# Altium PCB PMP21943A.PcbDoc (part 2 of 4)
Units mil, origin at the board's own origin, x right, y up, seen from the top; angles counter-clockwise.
Board outline 5100 x 3900 mil, 8 copper layers (Top Layer, Signal Layer 1, Signal Layer 2, Signal Layer 3, Signal Layer 4, Signal Layer 5, Signal Layer 6, Bottom Layer), stack 61.6 mil thick; 371 components, 163 nets, 967 pads, 1147 vias.
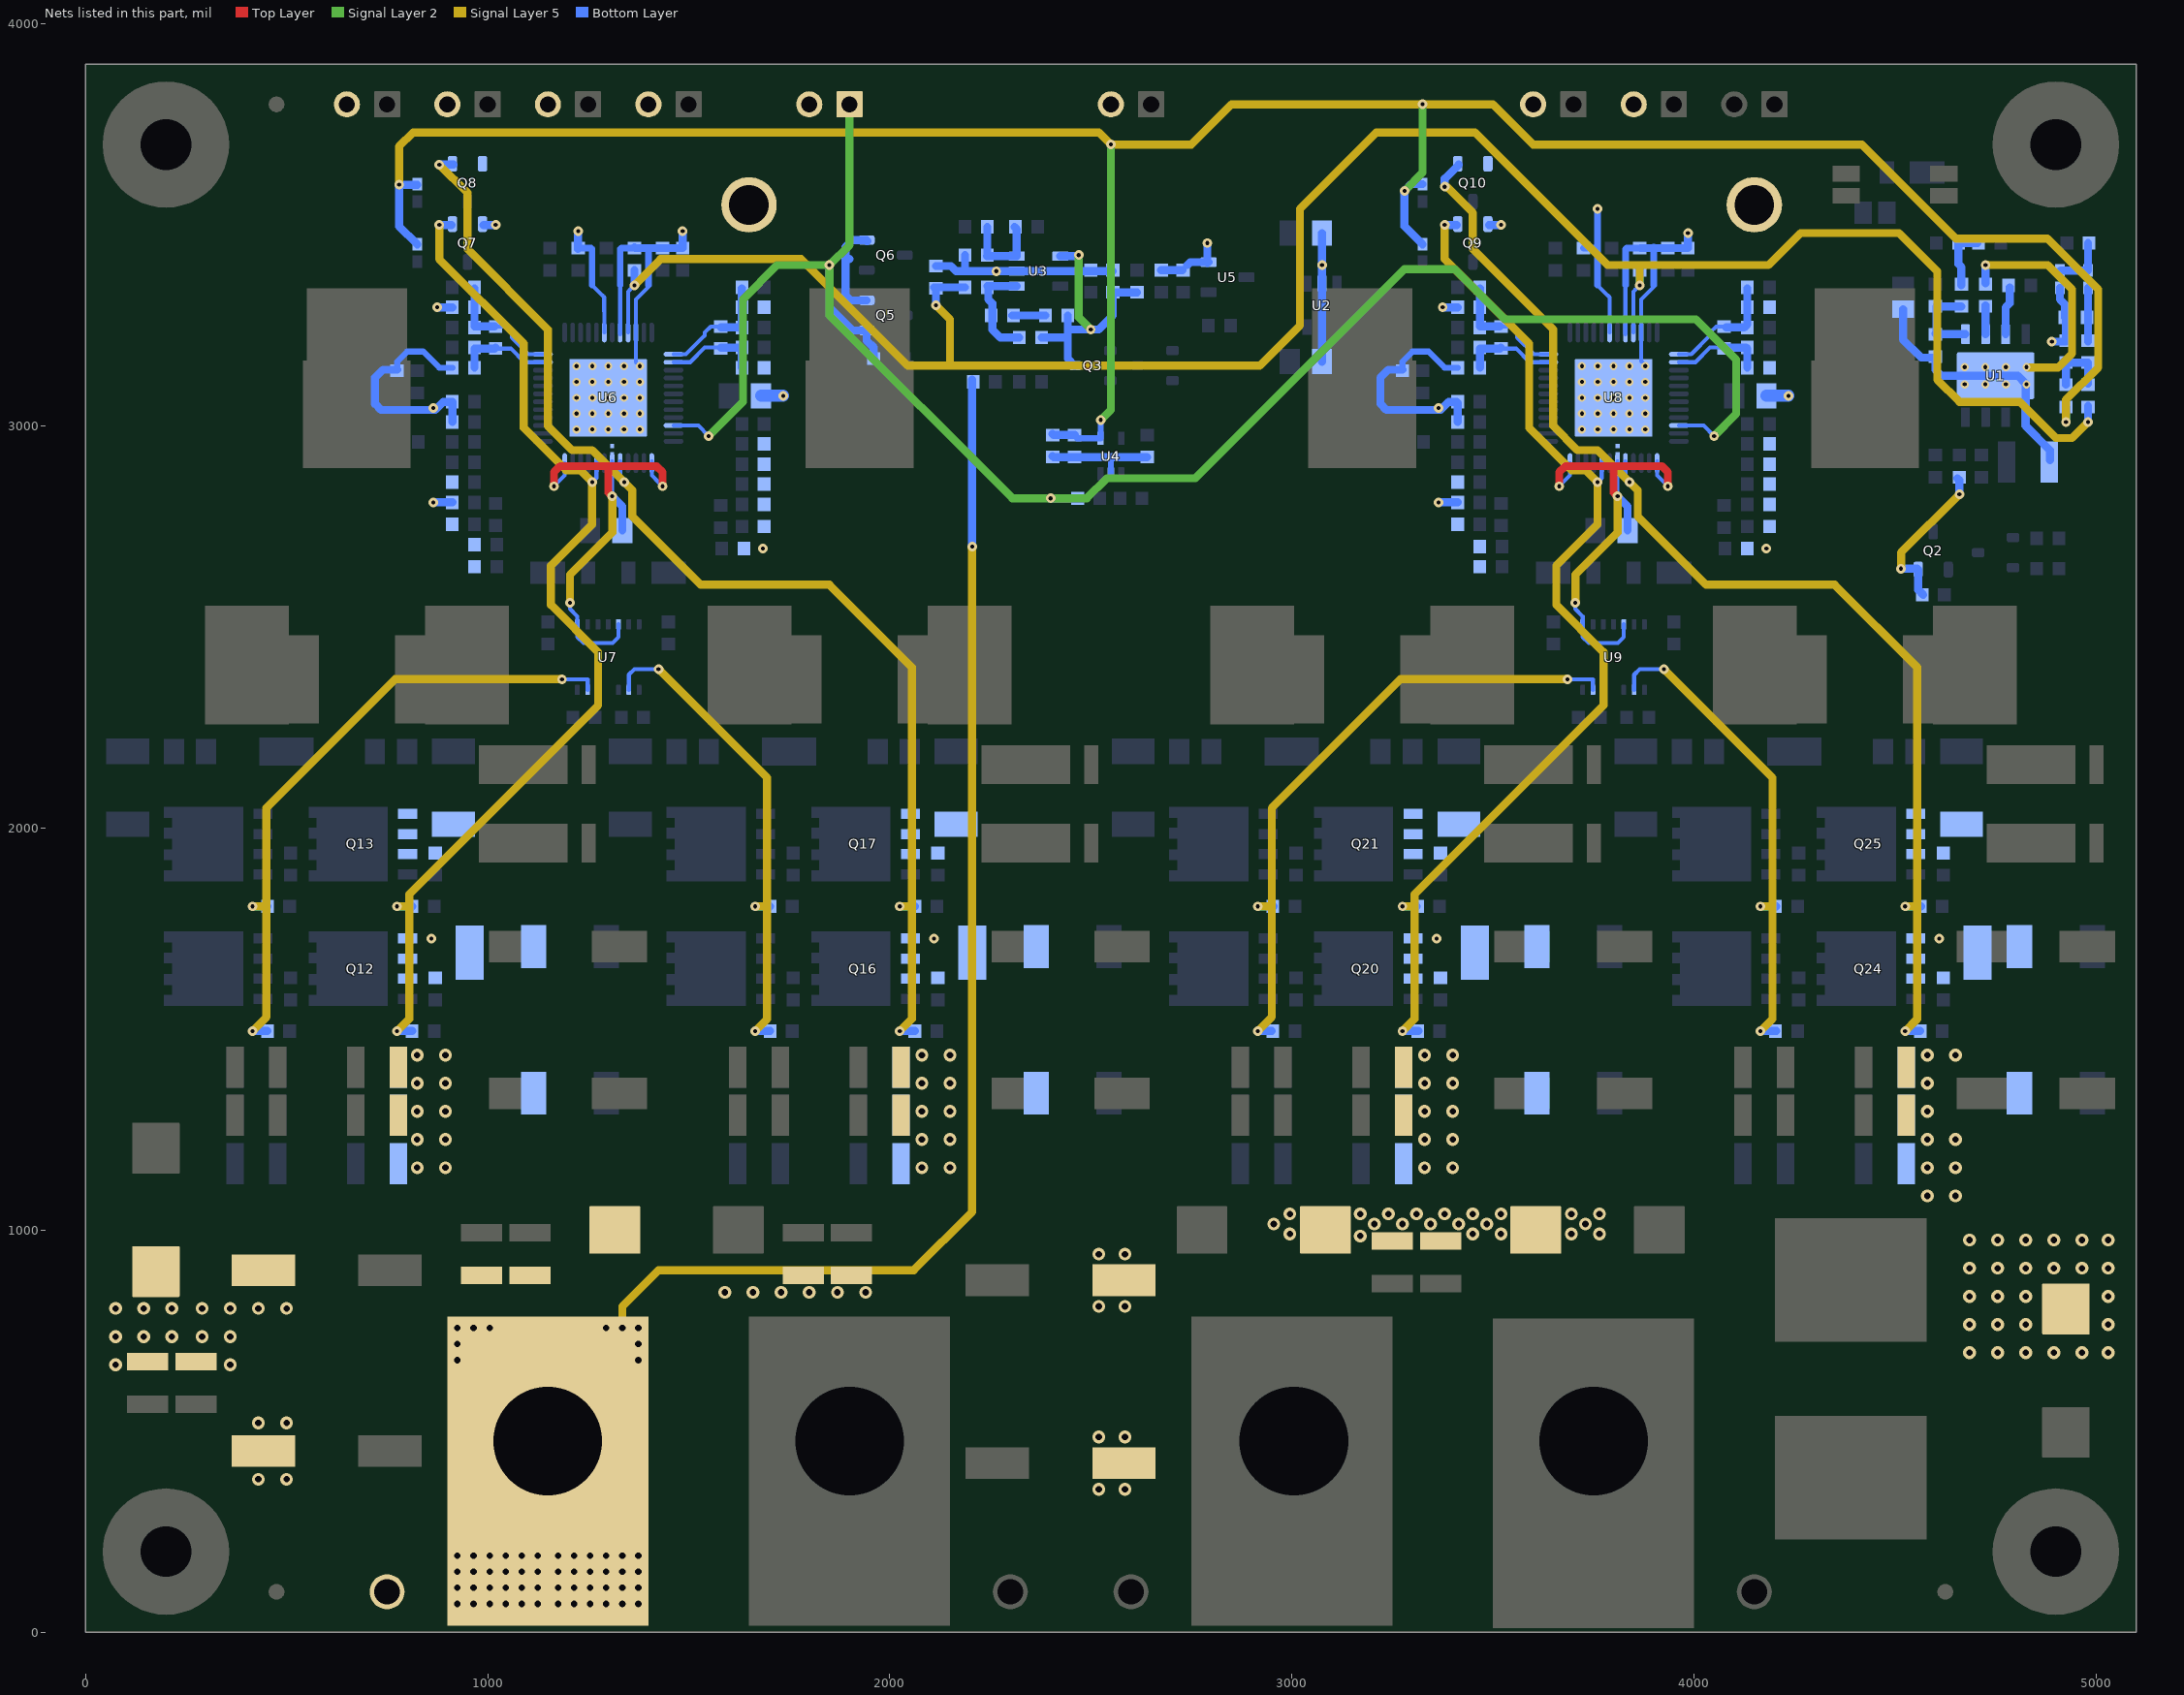
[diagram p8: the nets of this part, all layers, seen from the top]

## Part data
C1 C8: library part CMP-0007995-2, "CAP, CERM, 10 uF, 16 V, +/- 10%, X7R, 0805", Cap_Case=0805, Manufacturer="Samsung Electro-Mechanics", PartNumber=CL21B106KOQNNNE, TempCo=X7R, Tolerance_%=10%, Value1=Unknown, Value2=16V, ValueDisplayed=10uF
C2 C11: library part CMP-0007468-5, "CAP, CERM, 0.01 uF, 100 V, +/- 10%, X7R, 0603", Cap_Case=0603, Manufacturer=MuRata, PartNumber=GRM188R72A103KA01D, Supplier Part Number 1=GRM188R72A103KA01D-ND, TempCo=X7R, Tolerance_%=10%, Value1=Unknown, Value2=100V, ValueDisplayed=0.01uF
C3 C24 C45: library part CMP-0007891-2, "CAP, CERM, 1 uF, 100 V, +/- 10%, X7S, 0805", Cap_Case=0805, Manufacturer=TDK, PartNumber=C2012X7S2A105K125AB, Supplier Part Number 1=445-5205-1-ND, TempCo=X7S, Tolerance_%=10%, Value1="0.008255 ohm", Value2=100V, ValueDisplayed=1uF
C4: library part CMP-0006883-4, "CAP, CERM, 0.015 uF, 100 V, +/- 10%, X7R, 0603", Cap_Case=0603, Manufacturer=Kemet, PartNumber=C0603C153K1RACTU, Supplier Part Number 1=399-3474-1-ND, TempCo=X7R, Tolerance_%=10%, Value1=Unknown, Value2=100V, ValueDisplayed=0.015uF
C5: library part CMP-0007379-4, "CAP, CERM, 1 uF, 16 V, +/- 10%, X7R, 0603", Cap_Case=0603, Manufacturer=MuRata, PartNumber=GRM188R71C105KA12D, Supplier Part Number 1=490-3900-1-ND, TempCo=X7R, Tolerance_%=10%, Value1="0.011 ohm", Value2=16V, ValueDisplayed=1uF
C6 C29 C50: library part CMP-0007867-2, "CAP, CERM, 2.2 uF, 16 V, +/- 10%, X7R, 0805", Cap_Case=0805, Manufacturer=TDK, PartNumber=C2012X7R1C225K125AB, Supplier Part Number 1=445-1420-1-ND, TempCo=X7R, Tolerance_%=10%, Value1="0.0049 ohm", Value2=16V, ValueDisplayed=2.2uF
C7: library part CMP-0007467-4, "CAP, CERM, 1000 pF, 100 V, +/- 10%, X7R, 0603", Cap_Case=0603, Manufacturer=MuRata, PartNumber=GRM188R72A102KA01D, Supplier Part Number 1=490-1472-1-ND, TempCo=X7R, Tolerance_%=10%, Value1=Unknown, Value2=100V, ValueDisplayed=1000pF
C9: library part CMP-0009180-2, "CAP, CERM, 1 uF, 100 V, +/- 10%, X7R, 1210", Cap_Case=1210, Manufacturer=MuRata, PartNumber=GRM32CR72A105KA35L, Supplier Part Number 1=GRM32CR72A105KA35L-ND, TempCo=X7R, Tolerance_%=10%, Value1=Unknown, Value2=100V, ValueDisplayed=1uF
C10 C21 C26 C27 C31 C35 C36 C38 C39 C40 C42 C47 C48 C52 C56 C57 C59 C60 C61: library part CMP-0006841-4, "CAP, CERM, 100 pF, 50 V, +/- 5%, C0G/NP0, 0603", Cap_Case=0603, Manufacturer=Kemet, PartNumber=C0603C101J5GACTU, Supplier Part Number 1=399-1061-1-ND, TempCo=C0G/NP0, Tolerance_%=5%, Value1=Unknown, Value2=50V, ValueDisplayed=100pF
C12 C16: library part CMP-0007469-4, "CAP, CERM, 0.1 uF, 100 V, +/- 10%, X7R, 0603", Cap_Case=0603, Manufacturer=MuRata, PartNumber=GRM188R72A104KA35D, Supplier Part Number 1=490-3285-1-ND, TempCo=X7R, Tolerance_%=10%, Value1=Unknown, Value2=100V, ValueDisplayed=0.1uF
C13 C18 C19 C20 C23 C41 C44: library part CMP-0006993-4, "CAP, CERM, 1000 pF, 100 V, +/- 5%, C0G/NP0, 0603", Cap_Case=0603, Manufacturer=TDK, PartNumber=C1608C0G2A102J080AA, Supplier Part Number 1=445-2312-1-ND, TempCo=C0G/NP0, Tolerance_%=5%, Value1="0.0589 ohm", Value2=100V, ValueDisplayed=1000pF
C14 C22 C33 C37 C43 C54 C58: library part CMP-0006727-4, "CAP, CERM, 0.01 uF, 100 V, +/- 10%, X7R, 0603", Cap_Case=0603, Manufacturer=AVX, PartNumber=06031C103KAT2A, Supplier Part Number 1=478-1205-1-ND, TempCo=X7R, Tolerance_%=10%, Value1="0.098 ohm", Value2=100V, ValueDisplayed=0.01uF
C15: library part CMP-0007457-4, "CAP, CERM, 0.047 uF, 50 V, +/- 10%, X7R, 0603", Cap_Case=0603, Manufacturer=MuRata, PartNumber=GRM188R71H473KA61D, Supplier Part Number 1=490-3287-1-ND, TempCo=X7R, Tolerance_%=10%, Value1=Unknown, Value2=50V, ValueDisplayed=0.047uF
C17: library part CMP-0007196-4, "CAP, CERM, 22 pF, 50 V, +/- 5%, C0G/NP0, 0603", Cap_Case=0603, Manufacturer=MuRata, PartNumber=GRM1885C1H220JA01D, Supplier Part Number 1=490-1411-1-ND, TempCo=C0G/NP0, Tolerance_%=5%, Value1=Unknown, Value2=50V, ValueDisplayed=22pF
C25 C28 C32 C34 C46 C49 C53 C55: library part CMP-0007047-4, "CAP, CERM, 0.22 uF, 50 V, +/- 10%, X7R, 0603", Cap_Case=0603, Manufacturer=TDK, PartNumber=C1608X7R1H224K080AB, Supplier Part Number 1=445-7408-1-ND, TempCo=X7R, Tolerance_%=10%, Value1="0.021699 ohm", Value2=50V, ValueDisplayed=0.22uF
C30 C51: library part CMP-0007405-4, "CAP, CERM, 1 uF, 25 V, +/- 10%, X7R, 0603", Cap_Case=0603, Manufacturer=MuRata, PartNumber=GRM188R71E105KA12D, Supplier Part Number 1=490-5307-1-ND, TempCo=X7R, Tolerance_%=10%, Value1=Unknown, Value2=25V, ValueDisplayed=1uF
C62 C63 C80 C88 C97 C98 C114 C122: library part CMP-0007518-2, "CAP, CERM, 100 pF, 100 V, +/- 10%, C0G/NP0, 0805", Cap_Case=0805, Manufacturer=AVX, PartNumber=08051A101KAT2A, Supplier Part Number 1=478-3733-1-ND, TempCo=C0G/NP0, Tolerance_%=10%, Value1="0.356 ohm", Value2=100V, ValueDisplayed=100pF
C64 C89 C99 C123: library part CMP-0012274-3, "CAP, Aluminum Polymer, 100 uF, 63 V, +/- 20%, 0.024 ohm, SMD, 2-Leads, Dia 10.5mm, Pin Spacing 8mm SMD", Cap_Case=10x12.7mm, Manufacturer=Nichicon, PartNumber=PCR1J101MCL1GS, Supplier Part Number 1=493-13783-1-ND, Tolerance_%=20%, Value1="0.024 ohm", Value2=63V, ValueDisplayed=100uF
C65 C66 C67 C68 C69 C70 C71 C75 C76 C77 C78 C79 C83 C84 C85 C86 C87 C90 C91 C92 C93 C94 C95 C96 C100 C101 C102 C103 C104 C105 C106 C109 C110 C111 C112 C113 C117 C118 C119 C120 C121 C124 C125 C126 C127 C128 C129 C130: library part CMP-0082268-1, "CAP, CERM, 4.7 µF, 100 V,+/- 10%, X7S, AEC-Q200 Grade 1, 1210", Cap_Case=1210, Manufacturer=MuRata, Supplier Part Number 1=490-14484-1-ND, TempCo=X7S, Tolerance_%=10%, Value1="0.001 ohm", Value2=100V, ValueDisplayed=4.7µF
C72 C73 C81 C82 C107 C108 C115 C116: library part CMP-0012276-3, "CAP, Aluminum Polymer, 39 uF, 80 V, +/- 20%, 0.035 ohm, D8xL12mm SMD", Cap_Case=8x12mm, Manufacturer=Nichicon, PartNumber=PCR1K390MCL1GS, Supplier Part Number 1=493-13786-1-ND, Tolerance_%=20%, Value1="0.035 ohm", Value2=80V, ValueDisplayed=39uF
C74: library part CMP-0011313-2, "CAP, AL, 100 uF, 100 V, +/- 20%, 0.24 ohm, SMD", Cap_Case=LH0, Manufacturer=Chemi-Con, PartNumber=EMVH101GDA101MLH0S, Supplier Part Number 1=565-2344-1-ND, Tolerance_%=20%, Value1="0.24 ohm", Value2=100V, ValueDisplayed=100uF
D1 D5 D6 D9 D10: library part CMP-0077034-2, "Diode, Schottky, 150 V, 1 A, PowerDI123", Manufacturer="Diodes Inc.", Value1=1A, Value2=0.82V
D2 D3 D4 D7 D8 D11: library part CMP-0076957-3, "Diode, Switching, 75 V, 0.3 A, SOD-523", Manufacturer="Micro Commercial Components", Value1=0.3A, Value2=1.25V
FID1 FID2 FID3: library part CMP-0077181-1, "Fiducial mark.  There is nothing to buy or mount.", Manufacturer=N/A
H1 H2 H3 H4: library part CMP-0003617-1, "Machine Screw, Round, #4-40 x 1/4, Nylon, Philips panhead", Manufacturer="B&F Fastener Supply", Supplier Part Number 1=H542-ND
H5 H6 H7 H8: library part CMP-0003655-1, "Standoff, Hex, 1\"L #4-40 Aluminum", Manufacturer=Keystone, PartNumber=2205, Supplier Part Number 1=36-2205-ND
J1 J2 J3 J4 J5 J6 J7 J8 J9: library part CMP-0075483-1, "Header, 100mil, 2x1, Gold, TH", Manufacturer=Samtec, PartNumber=HTSW-102-07-G-S, Supplier Part Number 1=SAM8736-ND
J10 J11 J12 J13: library part CMP-0055387-2, "Standard Banana Jack, Uninsulated, 15A", Manufacturer="Cinch Connectivity", PartNumber=108-0740-001, Supplier Part Number 1=J147-ND
L1: library part CMP-0012798-2, "Coupled inductor, 680 uH, 0.38 A, 5.15 ohm, SMD", Manufacturer=Coiltronics, Supplier Part Number 1=513-1278-1-ND, ValueDisplayed=680uH
L2 L5 L7 L9: library part CMP-0087002-1, "Surface Mount Power Inductor, WE-HCF Series, 15 H, 15%, Shielded, 2400 ohm, 30 A", Manufacturer="Wurth Electronics"
L3 L4 L6 L8 L10: library part CMP-0085710-1, "Inductor, Shielded, Ferrite, 330 nH, 39 A, 0.000198 ohm, SMD", Manufacturer=TDK, Value1="0.000198 ohm", Value2=39A, ValueDisplayed=330nH
LBL1: library part CMP-0003624-1, "Thermal Transfer Printable Labels, 1.250\" W x 0.250\" H - 10,000 per roll", Manufacturer=Brady, PartNumber=THT-13-457-10, Supplier Part Number 1=04H3909
Logo1: library part CMP-0074847-1, "FCC_disclaimer"
LOGO2 LOGO3: library part CMP-0074837-1, "IEC 61010-1 Hot Surface Warning"
LOGO4: library part CMP-0074835-1, "IEC 61010-1 High Voltage Warning"
NT1 NT2: library part CMP-0078142-3, "Single point connection between nets.", Manufacturer=N/A
Q1 Q3 Q4: library part CMP-0000338-2, "Transistor, PNP, 80 V, 0.5 A, SOT-23", Manufacturer="ON Semiconductor", Supplier Part Number 1=MMBTA56LT1GOSDKR-ND, Value1="0.5 A"
Q2 Q5 Q6 Q7 Q8 Q9 Q10: library part CMP-0000771-1, "MOSFET, N-CH, 60 V, 0.24 A, SOT-23", Alternate Manufacturer=None, Manufacturer=Vishay-Siliconix, Supplier Part Number 1=2N7002E-T1-E3CT-ND, Value1=1, Value2="0.4 nC"
Q11 Q12 Q13 Q14 Q15 Q16 Q17 Q18 Q19 Q20 Q21 Q22 Q23 Q24 Q25 Q26: library part CMP-0067566-1, "MOSFET, N-CH, 150 V, 56 A, PG-TDSON-8", Alternate Manufacturer=None, Manufacturer="Infineon Technologies", Supplier Part Number 1=BSC160N15NS5ATMA1-ND, Value1="? ohm", Value2="19 nC"
R1 R2 R7 R15: library part CMP-0025698-4, "RES, 100 k, 5%, 0.1 W, AEC-Q200 Grade 0, 0603", Manufacturer=Vishay-Dale, PartNumber=CRCW0603100KJNEA, Power_W=100mW, Supplier Part Number 1=541-100KGCT-ND, TempCo="200 ppm/C", Tolerance_%=5%, Value2=0.1W, Value_Code=100k
R3 R13 R27 R29 R31 R49 R51: library part CMP-0021990-4, "RES, 100 k, 1%, 0.1 W, AEC-Q200 Grade 0, 0603", Manufacturer=Vishay-Dale, PartNumber=CRCW0603100KFKEA, Power_W=100mW, Supplier Part Number 1=541-100KHCT-ND, TempCo="100 ppm/C", Tolerance_%=1%, Value2=0.1W, Value_Code=100k
R4: library part CMP-0022496-4, "RES, 560 k, 1%, 0.1 W, AEC-Q200 Grade 0, 0603", Manufacturer=Vishay-Dale, PartNumber=CRCW0603560KFKEA, Power_W=100mW, Supplier Part Number 1=541-560KHCT-ND, TempCo="100 ppm/C", Tolerance_%=1%, Value2=0.1W, Value_Code=560k
R5: library part CMP-0025782-4, "RES, 30 k, 5%, 0.1 W, AEC-Q200 Grade 0, 0603", Manufacturer=Vishay-Dale, PartNumber=CRCW060330K0JNEA, Power_W=100mW, Supplier Part Number 1=541-30KGCT-ND, TempCo="200 ppm/C", Tolerance_%=5%, Value2=0.1W, Value_Code=30k0, ValueDisplayed=30k
R6: library part CMP-0022050-4, "RES, 143 k, 1%, 0.1 W, AEC-Q200 Grade 0, 0603", Manufacturer=Vishay-Dale, PartNumber=CRCW0603143KFKEA, Power_W=100mW, Supplier Part Number 1=541-143KHCT-ND, TempCo="100 ppm/C", Tolerance_%=1%, Value2=0.1W, Value_Code=143k
R8: library part CMP-0022454-4, "RES, 4.53 k, 1%, 0.1 W, AEC-Q200 Grade 0, 0603", Manufacturer=Vishay-Dale, PartNumber=CRCW06034K53FKEA, Power_W=100mW, Supplier Part Number 1=541-4.53KHCT-ND, TempCo="100 ppm/C", Tolerance_%=1%, Value2=0.1W, Value_Code=4k53, ValueDisplayed=4.53k
R9 R21 R36 R37 R56 R57: library part CMP-0022204-4, "RES, 20.0 k, 1%, 0.1 W, AEC-Q200 Grade 0, 0603", Manufacturer=Vishay-Dale, PartNumber=CRCW060320K0FKEA, Power_W=100mW, Supplier Part Number 1=541-20.0KHCT-ND, TempCo="100 ppm/C", Tolerance_%=1%, Value2=0.1W, Value_Code=20k0, ValueDisplayed=20.0k
R10 R20 R22 R35 R55: library part CMP-0021998-4, "RES, 10.0 k, 1%, 0.1 W, AEC-Q200 Grade 0, 0603", Manufacturer=Vishay-Dale, PartNumber=CRCW060310K0FKEA, Power_W=100mW, Supplier Part Number 1=541-10.0KHCT-ND, TempCo="100 ppm/C", Tolerance_%=1%, Value2=0.1W, Value_Code=10k0, ValueDisplayed=10.0k
R11: library part CMP-0022503-4, "RES, 57.6 k, 1%, 0.1 W, AEC-Q200 Grade 0, 0603", Manufacturer=Vishay-Dale, PartNumber=CRCW060357K6FKEA, Power_W=100mW, Supplier Part Number 1=541-57.6KHCT-ND, TempCo="100 ppm/C", Tolerance_%=1%, Value2=0.1W, Value_Code=57k6, ValueDisplayed=57.6k
R12: library part CMP-0021991-4, "RES, 100, 1%, 0.1 W, AEC-Q200 Grade 0, 0603", Manufacturer=Vishay-Dale, PartNumber=CRCW0603100RFKEA, Power_W=100mW, Supplier Part Number 1=541-100HCT-ND, TempCo="100 ppm/C", Tolerance_%=1%, Value2=0.1W, Value_Code=100R, ValueDisplayed=100
R14: library part CMP-0022562-4, "RES, 6.65 k, 1%, 0.1 W, AEC-Q200 Grade 0, 0603", Manufacturer=Vishay-Dale, PartNumber=CRCW06036K65FKEA, Power_W=100mW, Supplier Part Number 1=541-6.65KHCT-ND, TempCo="100 ppm/C", Tolerance_%=1%, Value2=0.1W, Value_Code=6k65, ValueDisplayed=6.65k
R16: library part CMP-0022449-4, "RES, 4.02 k, 1%, 0.1 W, AEC-Q200 Grade 0, 0603", Manufacturer=Vishay-Dale, PartNumber=CRCW06034K02FKEA, Power_W=100mW, Supplier Part Number 1=541-4.02KHCT-ND, TempCo="100 ppm/C", Tolerance_%=1%, Value2=0.1W, Value_Code=4k02, ValueDisplayed=4.02k
R17: library part CMP-0022945-5, "RES, 24.0 k, 1%, 0.1 W, 0603", Manufacturer=Yageo, PartNumber=RC0603FR-0724KL, Power_W=100mW, Supplier Part Number 1=311-24.0KHRCT-ND, TempCo="100 ppm/C", Tolerance_%=1%, Value2=0.1W, Value_Code=24k0, ValueDisplayed=24.0k
R18 R24 R72 R78 R79 R81 R89 R95 R96 R98 R102 R108 R109 R111 R119 R125 R126 R128: library part CMP-0025697-4, "RES, 0, 5%, 0.1 W, AEC-Q200 Grade 0, 0603", Manufacturer=Vishay-Dale, PartNumber=CRCW06030000Z0EA, Power_W=100mW, Supplier Part Number 1=541-0.0GCT-ND, TempCo="200 ppm/C", Tolerance_%=5%, Value2=0.1W, Value_Code=0000, ValueDisplayed=0
R19: library part CMP-0022458-4, "RES, 4.99 k, 1%, 0.1 W, AEC-Q200 Grade 0, 0603", Manufacturer=Vishay-Dale, PartNumber=CRCW06034K99FKEA, Power_W=100mW, Supplier Part Number 1=541-4.99KHCT-ND, TempCo="100 ppm/C", Tolerance_%=1%, Value2=0.1W, Value_Code=4k99, ValueDisplayed=4.99k
R23: library part CMP-0022206-4, "RES, 20.0, 1%, 0.1 W, AEC-Q200 Grade 0, 0603", Manufacturer=Vishay-Dale, PartNumber=CRCW060320R0FKEA, Power_W=100mW, Supplier Part Number 1=541-20.0HCT-ND, TempCo="100 ppm/C", Tolerance_%=1%, Value2=0.1W, Value_Code=20R0, ValueDisplayed=20.0
R25: library part CMP-0022637-4, "RES, 8.66 k, 1%, 0.1 W, AEC-Q200 Grade 0, 0603", Manufacturer=Vishay-Dale, PartNumber=CRCW06038K66FKEA, Power_W=100mW, Supplier Part Number 1=541-8.66KHCT-ND, TempCo="100 ppm/C", Tolerance_%=1%, Value2=0.1W, Value_Code=8k66, ValueDisplayed=8.66k
R26: library part CMP-0025736-4, "RES, 1.0 M, 5%, 0.1 W, AEC-Q200 Grade 0, 0603", Manufacturer=Vishay-Dale, PartNumber=CRCW06031M00JNEA, Power_W=100mW, Supplier Part Number 1=541-1.0MGCT-ND, TempCo="200 ppm/C", Tolerance_%=5%, Value2=0.1W, Value_Code=1M00, ValueDisplayed=1.0M
R28: library part CMP-0022234-4, "RES, 249 k, 1%, 0.1 W, AEC-Q200 Grade 0, 0603", Manufacturer=Vishay-Dale, PartNumber=CRCW0603249KFKEA, Power_W=100mW, Supplier Part Number 1=541-249KHCT-ND, TempCo="100 ppm/C", Tolerance_%=1%, Value2=0.1W, Value_Code=249k
R30 R39 R48 R50 R59 R68: library part CMP-0022066-4, "RES, 15.0 k, 1%, 0.1 W, AEC-Q200 Grade 0, 0603", Manufacturer=Vishay-Dale, PartNumber=CRCW060315K0FKEA, Power_W=100mW, Supplier Part Number 1=541-15.0KHCT-ND, TempCo="100 ppm/C", Tolerance_%=1%, Value2=0.1W, Value_Code=15k0, ValueDisplayed=15.0k
R32 R45 R52 R65: library part CMP-0022374-4, "RES, 3.24 k, 1%, 0.1 W, AEC-Q200 Grade 0, 0603", Manufacturer=Vishay-Dale, Power_W=100mW, Supplier Part Number 1=541-3.24KHCT-ND, TempCo="100 ppm/C", Tolerance_%=1%, Value2=0.1W, Value_Code=3k24, ValueDisplayed=3.24k
R33 R34 R40 R53 R54 R60 R71 R73 R74 R80 R88 R92 R93 R97 R101 R103 R104 R110 R118 R122 R123 R127: library part CMP-0022447-4, "RES, 49.9 k, 1%, 0.1 W, AEC-Q200 Grade 0, 0603", Manufacturer=Vishay-Dale, PartNumber=CRCW060349K9FKEA, Power_W=100mW, Supplier Part Number 1=541-49.9KHCT-ND, TempCo="100 ppm/C", Tolerance_%=1%, Value2=0.1W, Value_Code=49k9, ValueDisplayed=49.9k
R38 R43 R58 R63 R76 R77 R90 R91 R106 R107 R120 R121: library part CMP-0025776-4, "RES, 2.0, 5%, 0.1 W, AEC-Q200 Grade 0, 0603", Manufacturer=Vishay-Dale, PartNumber=CRCW06032R00JNEA, Power_W=100mW, Supplier Part Number 1=541-2.0GCT-ND, TempCo="200 ppm/C", Tolerance_%=5%, Value2=0.1W, Value_Code=2R00, ValueDisplayed=2.0
R41 R61: library part CMP-0022249-4, "RES, 26.7 k, 1%, 0.1 W, AEC-Q200 Grade 0, 0603", Manufacturer=Vishay-Dale, PartNumber=CRCW060326K7FKEA, Power_W=100mW, Supplier Part Number 1=541-26.7KHCT-ND, TempCo="100 ppm/C", Tolerance_%=1%, Value2=0.1W, Value_Code=26k7, ValueDisplayed=26.7k
R42 R62: library part CMP-0022239-4, "RES, 24.9, 1%, 0.1 W, AEC-Q200 Grade 0, 0603", Manufacturer=Vishay-Dale, Power_W=100mW, Supplier Part Number 1=541-24.9HCT-ND, TempCo="100 ppm/C", Tolerance_%=1%, Value2=0.1W, Value_Code=24R9, ValueDisplayed=24.9
R44 R64: library part CMP-0022410-4, "RES, 40.2 k, 1%, 0.1 W, AEC-Q200 Grade 0, 0603", Manufacturer=Vishay-Dale, PartNumber=CRCW060340K2FKEA, Power_W=100mW, Supplier Part Number 1=541-40.2KHCT-ND, TempCo="100 ppm/C", Tolerance_%=1%, Value2=0.1W, Value_Code=40k2, ValueDisplayed=40.2k
R46 R66: library part CMP-0022418-4, "RES, 42.2 k, 1%, 0.1 W, AEC-Q200 Grade 0, 0603", Manufacturer=Vishay-Dale, PartNumber=CRCW060342K2FKEA, Power_W=100mW, Supplier Part Number 1=541-42.2KHCT-ND, TempCo="100 ppm/C", Tolerance_%=1%, Value2=0.1W, Value_Code=42k2, ValueDisplayed=42.2k
R47 R67: library part CMP-0022098-4, "RES, 18.7 k, 1%, 0.1 W, AEC-Q200 Grade 0, 0603", Manufacturer=Vishay-Dale, PartNumber=CRCW060318K7FKEA, Power_W=100mW, Supplier Part Number 1=541-18.7KHCT-ND, TempCo="100 ppm/C", Tolerance_%=1%, Value2=0.1W, Value_Code=18k7, ValueDisplayed=18.7k
R69 R75 R84 R94 R99 R105 R114 R124: library part CMP-0016049-3, "RES, 10, 5%, 0.75 W, AEC-Q200 Grade 0, 2010", Manufacturer=Vishay-Dale, PartNumber=CRCW201010R0JNEF, Power_W=750mW, Supplier Part Number 1=541-10.0WCT-ND, TempCo="200 ppm/C", Tolerance_%=5%, Value2=0.75W, Value_Code=10R0, ValueDisplayed=10
R70 R87 R100 R117: library part CMP-0015287-2, "RES, 0.001, 1%, 3 W, 6.6x3x6.9mm", Manufacturer=Vishay-Dale, PartNumber=WSL27261L000FEB, Power_W=3W, Supplier Part Number 1=WSLQ-.001CT-ND, TempCo="75 ppm/C", Tolerance_%=1%, Value_Code=1L000, ValueDisplayed=0.001
R82 R83 R85 R86 R112 R113 R115 R116: library part CMP-0016530-2, "RES, 0.5, 1%, 1 W, 2010", Manufacturer="Stackpole Electronics Inc", PartNumber=CSRN2010FKR500, Power_W=1W, Supplier Part Number 1=CSRN2010FKR500CT-ND, TempCo="250 ppm/C", Tolerance_%=1%, Value_Code=R500, ValueDisplayed=0.5
T1 T2 T3 T4: library part CMP-0075010-1, "Terminal 70A Lug", Manufacturer=Panduit, PartNumber=CXS70-14-C, Supplier Part Number 1=CXS70-14-C-ND
TP1 TP2: library part CMP-0055121-1, "Terminal, Turret, TH, Triple", Manufacturer=Keystone, PartNumber=1598-2, Supplier Part Number 1=36-1598-2-ND
TP3 TP4 TP9 TP10 TP11 TP12 TP13 TP14: library part CMP-0055152-1, "Test Point, Miniature, SMT", Manufacturer=Keystone, PartNumber=5015, Supplier Part Number 1=36-5015TR-ND
TP5 TP7: library part CMP-0055148-1, "Test Point, Multipurpose, Black, TH", Color=Black, Manufacturer=Keystone, PartNumber=5011, Supplier Part Number 1=36-5011-ND
TP6: library part CMP-0055147-1, "Test Point, Multipurpose, Red, TH", Color=Red, Manufacturer=Keystone, PartNumber=5010, Supplier Part Number 1=36-5010-ND
TP8: library part CMP-0055149-1, "Test Point, Multipurpose, White, TH", Color=White, Manufacturer=Keystone, PartNumber=5012, Supplier Part Number 1=36-5012-ND
U1: library part CMP-0066088-2, "7.5-100V Wide Vin, 300mA Constant On-Time Synchronous Buck Regulator, DDA0008B (SOIC-8)", Alternate Manufacturer="Texas Instruments", Alternate PartNumber=LM5018MR/NOPB, PartNumber=LM5018MRX/NOPB
U2: library part CMP-0066783-1, "150-mA, 30-V, Ultra-Low IQ, Wide Input Low-Dropout Regulator with Reverse Current Protection, DBV0005A (SOT-23-5)", Alternate Manufacturer="Texas Instruments", Alternate PartNumber=TPS70950DBVT, PartNumber=TPS70950DBVR
U3: library part CMP-0068647-3, "RRIO, High Output Current & Unlimited Cap Load Op Amp, DBV0005A (SOT-23-5)", Manufacturer="Texas Instruments", Operating Temperature Range="-40 to 85 C", Rating=Catalog
U4: library part CMP-0085889-2, "Small-Size Micropower Low-Voltage Comparator, DCK0005A (SOT-SC70-5)", Alternate Manufacturer="Texas Instruments", Alternate PartNumber=TLV7021DCKT, Operating Temperature Range="-40 to 125 C", Rating=Catalog
U5: library part CMP-0078976-1, "Precision Micropower Shunt Voltage Reference, DBZ0003A (SOT-23-3)", Alternate Manufacturer="Texas Instruments", Alternate PartNumber=LM4040AIM3X-2.0/NOPB, PartNumber=LM4040AIM3-2.0/NOPB
U6 U8: "Multiphase Bidirectional Current Controller, PHP0048C (HTQFP-48)", Alternate Manufacturer="Texas Instruments", Alternate PartNumber=LM5170QPHPTQ1, Operating Temperature Range="-40 to 150 C", PartNumber=LM5170QPHPRQ1, Rating=Automotive
U7 U9: library part CMP-0013548-2, "4A/6A Isolated Dual-Channel Gate Driver, NPL0013A (VLGA-13)", Alternate Manufacturer="Texas Instruments"
ZZ1: library part CMP-0003616-3
ZZ2: library part CMP-0077236-1
ZZ3: library part CMP-0077237-1
ZZ4: library part CMP-0077238-1

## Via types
v1: diameter 32, hole 16, Top Layer to Bottom Layer, tented both sides, 555 vias
v2: diameter 24, hole 10, Top Layer to Bottom Layer, tented both sides, 534 vias
v3: diameter 20, hole 10, Top Layer to Bottom Layer, tented both sides, 58 vias

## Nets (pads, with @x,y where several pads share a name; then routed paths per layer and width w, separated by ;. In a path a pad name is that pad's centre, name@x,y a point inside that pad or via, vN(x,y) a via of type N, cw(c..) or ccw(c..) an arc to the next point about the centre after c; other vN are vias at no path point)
+VOUT: C64.1 C65.1 C66.1 C89.1 C90.1 C91.1 C99.1 C100.1 C101.1 C123.1 C124.1 C125.1 J11.1 L3.1 L6.1 L8.1 L10.1 R12.1 T2.1 TP6.1 | length 3091.1
  Signal Layer 5 w20: v1(1335,756.27) 1335,810 1425,900 2060,900 2205,1045 v2(2205,2700)
  Bottom Layer w20: v2(2205,2700) R12.1@2205,3115
  other v1: 925,70 965,70 1005,70 1045,70 1085,70 1125,70 1175,70 1215,70 1255,70 1295,70 1335,70 1375,70 925,110 965,110 1005,110 1045,110 1085,110 1125,110 1175,110 1215,110 1255,110 1295,110 1335,110 1375,110 925,150 965,150 1005,150 1045,150 1085,150 1125,150 1175,150 1215,150 1255,150 1295,150 1335,150 1375,150 925,190 965,190 1005,190 1045,190 1085,190 1125,190 1175,190 1215,190 1255,190 1295,190 1335,190 1375,190 2520,355 2585,355 430,380 500,380 2520,485 2585,485 430,520 500,520 75,665 360,665 925,676.27 1375,676.27 925,716.27 1375,716.27 75,735 145,735 215,735 290,735 360,735 925,756.27 965,756.27 1005,756.27 1295,756.27 1375,756.27 75,805 145,805 215,805 290,805 360,805 430,805 500,805 2520,810 2585,810 1590,845 1660,845 1730,845 1800,845 1870,845 1940,845 2520,940 2585,940 3170,985 2995,990 3450,990 3520,990 3695,990 3765,990 2955,1015 3205,1015 3275,1015 3345,1015 3415,1015 3485,1015 3730,1015 2995,1040 3170,1040 3240,1040 3310,1040 3380,1040 3450,1040 3520,1040 3695,1040 3765,1040
-VIN: C5.2 C8.2 C9.2 C29.2 C50.2 C75.2 C76.2 C77.2 C78.2 C79.2 C83.2 C84.2 C85.2 C86.2 C87.2 C109.2 C110.2 C111.2 C112.2 C113.2 C117.2 C118.2 C119.2 C120.2 C121.2 L4.1 NT1.2 NT2.2 Q2.2 Q12.1 Q12.2 Q12.3 Q13.1 Q13.2 Q13.3 Q16.1 Q16.2 Q16.3 Q17.1 Q17.2 Q17.3 Q20.1 Q20.2 Q20.3 Q21.1 Q21.2 Q21.3 Q24.1 Q24.2 Q24.3 Q25.1 Q25.2 Q25.3 R7.1 R8.2 R9.1 R73.2 R74.2 R75.1 R82.1 R83.1 R85.1 R86.1 R92.2 R93.2 R94.1 R103.2 R104.2 R105.1 R112.1 R113.1 R115.1 R116.1 R122.2 R123.2 R124.1 TP4.1 TP10.1 TP12.1 TP14.1 U1.1 U1.9@4750,3125 U6.13 U6.18 U6.24 U7.1 U7.5 U8.13 U8.18 U8.24 U9.1 U9.5 | length 4217.5
  Top Layer w20: v2(1165,2850) 1165,2885 1180,2900 1300,2900 ; v2(1310,2825) 1300,2835 1300,2900 ; v2(1435,2850) 1435,2885 1420,2900 1300,2900 ; v2(3665,2850) 3665,2885 3680,2900 3800,2900 ; v2(3810,2825) 3800,2835 3800,2900 ; v2(3935,2850) 3935,2885 3920,2900 3800,2900
  Signal Layer 5 w20: v2(1205,2560) 1205,2630 1310,2735 v2(1310,2825) ; v2(3705,2560) 3705,2630 3810,2735 v2(3810,2825) ; v2(4515,2645) 4515,2685 v2(4660,2830) ; v2(4725,3400) 4880,3400 4940,3340 4940,3180 4905,3145 v3@4830,3145
  Bottom Layer w10: v2(1165,2850) 1165,2850.18 1191.73,2876.91 U6.24@1191.73,2907.6 ; v2(1205,2560) 1205,2545 1223.23,2526.77 U7.1@1223.23,2506.69 1223.23,2475 1238.23,2460 1310.59,2460 1325.59,2475 U7.5@1325.59,2506.69 ; U6.18@1309.84,2911.54 1309.84,2825.16 v2(1310,2825) ; U6.13@1408.27,2911.54 1408.27,2876.91 1424.87,2860.3 1424.87,2860.13 v2(1435,2850) ; v2(3665,2850) 3665,2850.18 3691.73,2876.91 U8.24@3691.73,2907.6 ; v2(3705,2560) 3705,2545 3723.23,2526.77 U9.1@3723.23,2506.69 3723.23,2475 3738.23,2460 3810.59,2460 3825.59,2475 U9.5@3825.59,2506.69 ; U8.18@3809.84,2911.54 3809.84,2825.16 v2(3810,2825) ; U8.13@3908.27,2911.54 3908.27,2876.91 3924.87,2860.3 3924.87,2860.13 v2(3935,2850)
  Bottom Layer w20: v2(1310,2825) 1335,2800 C29.2@1335,2740 ; v2(3810,2825) 3835,2800 C50.2@3835,2740 ; v2(4515,2645) Q2.2@4555,2645 ; C8.2@4520,3290.47 4520,3215 4565,3170 4600,3170 4600,3140 4615,3125 U1.9@4750,3125 4805,3125 4825,3105 U1.1@4825,3025 ; Q2.2@4557.6,2642.76 4557.6,2592.4 R7.1@4570,2580 ; R8.2@4655,2870 4660,2865 v2(4660,2830) ; C5.2@4725,3355 v2@4725,3395 ; U1.1@4825,3020 4825,3000 4885,2940 C9.2@4885,2915
  other v1: 4685,695 4755,695 4825,695 4895,695 4965,695 5030,695 4685,765 4755,765 4825,765 5030,765 4685,835 4755,835 4825,835 5030,835 4685,905 4755,905 4825,905 4895,905 4965,905 5030,905 4685,975 4755,975 4825,975 4895,975 4965,975 5030,975 4580,1085 4650,1085 825,1155 895,1155 2080,1155 2150,1155 3330,1155 3400,1155 4580,1155 4650,1155 825,1225 895,1225 2080,1225 2150,1225 3330,1225 3400,1225 4580,1225 4650,1225 825,1295 895,1295 2080,1295 2150,1295 3330,1295 3400,1295 4580,1295 825,1365 895,1365 2080,1365 2150,1365 3330,1365 3400,1365 4580,1365 825,1435 895,1435 2080,1435 2150,1435 3330,1435 3400,1435 4580,1435 4650,1435
  other v2: 860,1725 2110,1725 3360,1725 4610,1725
  other v3: 4673.23,3103.35 4724.41,3103.35 4775.59,3103.35 4826.77,3103.35 4673.23,3146.65 4724.41,3146.65 4775.59,3146.65 4826.77,3146.65
AGND: C3.2 C6.2 C12.2 C13.2 C14.2 C15.2 C16.1 C18.2 C19.2 C20.2 C21.1 C23.2 C24.2 C26.2 C27.2 C30.2 C31.2 C33.2 C35.2 C36.2 C38.2 C39.2 C40.2 C41.2 C42.1 C44.2 C45.2 C47.2 C48.2 C51.2 C52.2 C54.2 C56.2 C57.2 C59.2 C60.2 C61.2 D3.1 J2.2 J3.2 J4.2 J5.2 J6.2 J7.2 J8.2 J9.2 NT1.1 NT2.1 Q5.2 Q6.2 Q7.2 Q8.2 Q9.2 Q10.2 R15.2 R16.2 R22.2 R25.1 R30.2 R35.2 R37.1 R39.1 R41.1 R44.1 R46.1 R47.1 R48.1 R50.2 R55.2 R57.1 R59.1 R61.1 R64.1 R66.1 R67.1 R68.1 TP1.1 TP2.1 U2.2 U3.2 U4.2 U5.2 U6.42 U6.44 U6.46 U6.49 U8.42 U8.44 U8.46 U8.49 | length 5226.4
  Bottom Layer w10: 1260,3350 1260,3349.82 1284.7,3325.13 1284.87,3325.13 1290,3320 1290,3285 ; U6.42@1290.16,3232.4 1290.16,3289.11 ; U6.44@1329.53,3228.46 1329.53,3349.53 1330,3350 ; U6.49@1368.9,3158.58 1368.9,3228.46 1368.9,3315 1400,3346.1 1400,3350 ; 3760,3350 3760,3349.82 3784.7,3325.13 3784.87,3325.13 3790,3320 3790,3285 ; U8.42@3790.16,3232.4 3790.16,3289.11 ; U8.44@3829.53,3228.46 3829.53,3349.53 3830,3350 ; U8.46@3868.9,3228.46 3868.9,3315 3900,3346.1 3900,3350 ; U8.46@3868.9,3232.4 3868.9,3161.1 U8.49@3880,3150
  Bottom Layer w15: R37.1@775,3140 775,3160 800,3185 840,3185 880,3145 C27.2@912.44,3145 ; U4.2@2550,2880.71 2550,2920 ; R57.1@3275,3140 3275,3160 3300,3185 3340,3185 3380,3145 C48.2@3412.44,3145
  Bottom Layer w16: R35.2@1225,3442.56 1257.44,3442.56 1260,3440 1260,3350 ; 1330,3350 1330,3440 1332.56,3442.56 C31.2@1365,3442.56 ; 1400,3350 1400,3442.56 ; R55.2@3725,3442.56 3757.44,3442.56 3760,3440 ; 3760,3350 3760,3440 ; v2(3760,3540) 3760,3440 ; 3830,3350 3830,3440 3832.56,3442.56 C52.2@3865,3442.56 ; 3900,3350 3900,3442.56 3900,3445
  Bottom Layer w20: R37.1@775,3140 740,3140 720,3120 720,3055 735,3040 870,3040 890,3060 C30.2@910,3060 ; v2(865,2810) C21.1@912.44,2810 ; v2(875,3295) C26.2@912.44,3295 ; R44.1@912.44,3010 912.44,3057.56 C30.2@910,3060 ; C30.2@912.44,3060 C30.2@910,3060 ; Q7.2@990,3500 v2(1020,3500) ; R35.2@1225,3440 R35.2@1225,3442.56 v2(1225,3485) ; C31.2@1365,3445 1367.44,3442.56 1400,3442.56 R41.1@1435,3442.56 R39.1@1485,3442.56 v2(1485,3485) ; 1900,3415 1890,3415 ; Q5.2@1942.76,3312.4 1902.6,3312.4 1890,3325 1890,3415 ; Q6.2@1942.76,3460 Q6.2@1945,3460 ; Q6.2@1942.76,3462.4 1907.4,3462.4 1890,3445 1890,3415 ; R22.2@2115,3397.56 2152.44,3397.56 2165,3385 2185,3385 ; C14.2@2187.44,3425 2187.44,3387.44 2185,3385 ; C15.2@2405,2925 2407.56,2922.44 R25.1@2460,2922.44 C16.1@2640,2922.44 ; R16.2@2555,3385 U3.2@2315.87,3385 v2(2265,3385) 2185,3385 ; R15.2@2675,3387.56 C13.2@2727.44,3387.56 ; C13.2@2740,3400 2747.4,3407.4 U5.2@2790,3407.4 ; U5.2@2790,3405 U5.2@2790,3407.4 ; v2(2790,3455) U5.2@2790,3407.4 ; U5.2@2792.76,3407.4 U5.2@2790,3407.4 ; C6.2@3075,3160 U2.2@3075,3354.13 C3.2@3075,3480 ; R57.1@3275,3140 3240,3140 3220,3120 3220,3055 3235,3040 3370,3040 3390,3060 C51.2@3410,3060 ; v2(3365,2810) C42.1@3412.44,2810 ; v2(3375,3295) C47.2@3412.44,3295 ; R64.1@3412.44,3010 C51.2@3412.44,3057.56 ; Q9.2@3490,3500 v2(3520,3500) ; C52.2@3867.56,3442.56 3900,3442.56 R61.1@3935,3442.56 R59.1@3985,3442.56 ; R59.1@3985,3445 v2(3985,3480) ; v2(4890,3210) C18.2@4925,3210 ; D3.1@4910,3343.35 4910,3315 4922.44,3302.56 C19.2@4922.44,3270 ; C18.2@4925,3212.56 C19.2@4925,3270
  Bottom Layer w30: C24.2@1680,3075 v2(1735,3075) ; C45.2@4180,3075 v2(4235,3075)
  other v2: 1685,2695 4180,2695 865,3045 3365,3045 3075,3400
  other v3: 1221.26,2991.26 1260.63,2991.26 1300,2991.26 1339.37,2991.26 1378.74,2991.26 3721.26,2991.26 3760.63,2991.26 3800,2991.26 3839.37,2991.26 3878.74,2991.26 1221.26,3030.63 1260.63,3030.63 1300,3030.63 1339.37,3030.63 1378.74,3030.63 3721.26,3030.63 3760.63,3030.63 3800,3030.63 3839.37,3030.63 3878.74,3030.63 1221.26,3070 1260.63,3070 1300,3070 1339.37,3070 1378.74,3070 3721.26,3070 3760.63,3070 3800,3070 3839.37,3070 3878.74,3070 1221.26,3109.37 1260.63,3109.37 1300,3109.37 1339.37,3109.37 1378.74,3109.37 3721.26,3109.37 3760.63,3109.37 3800,3109.37 3839.37,3109.37 3878.74,3109.37 1221.26,3148.74 1260.63,3148.74 1300,3148.74 1339.37,3148.74 1378.74,3148.74 3721.26,3148.74 3760.63,3148.74 3800,3148.74 3839.37,3148.74 3878.74,3148.74
CS1A_1: C25.1 C26.1 R32.1 R76.1 U6.36 | length 297.2
  Bottom Layer w10: C25.1@1020,3247.56 1042.44,3247.56 1060,3230 1060,3220 1101.73,3178.27 U6.36@1137.6,3178.27
  Bottom Layer w20: R32.1@967.56,3342.56 C26.1@967.56,3295 967.56,3247.44 C25.1@1017.44,3247.44
CS1A_2: C46.1 C47.1 R52.1 R106.1 U8.36 | length 297.2
  Bottom Layer w10: C46.1@3520,3247.56 3542.44,3247.56 3560,3230 3560,3220 3601.73,3178.27 U8.36@3637.6,3178.27
  Bottom Layer w20: R52.1@3467.56,3342.56 C47.1@3467.56,3295 3467.56,3247.44 C46.1@3517.44,3247.44
CS1B_1: C25.2 C27.1 R77.1 U6.35 | length 232.6
  Bottom Layer w10: C25.2@1020,3192.44 1057.56,3192.44 1091.42,3158.58 U6.35@1137.6,3158.58
  Bottom Layer w20: C27.1@967.56,3145 967.56,3192.56 1017.56,3192.56 C25.2@1020,3195
CS1B_2: C46.2 C48.1 R107.1 U8.35 | length 232.6
  Bottom Layer w10: C46.2@3520,3192.44 3557.56,3192.44 3591.42,3158.58 U8.35@3637.6,3158.58
  Bottom Layer w20: C48.1@3467.56,3145 3467.56,3192.56 3517.56,3192.56 C46.2@3520,3195
CS2A_1: C34.2 C36.1 R45.2 R90.1 U6.1 | length 296.3
  Bottom Layer w10: U6.1@1462.4,3178.27 1493.27,3178.27 1540,3225 1540,3232.56 1555,3247.56 C34.2@1580,3247.56
  Bottom Layer w20: C34.2@1580,3245 1625,3245 1632.44,3252.44 C36.1@1632.44,3295 R45.2@1632.44,3342.44
CS2A_2: C55.2 C57.1 R65.2 R120.1 U8.1 | length 296.3
  Bottom Layer w10: U8.1@3962.4,3178.27 3993.27,3178.27 4040,3225 4040,3232.56 4055,3247.56 C55.2@4080,3247.56
  Bottom Layer w20: C55.2@4080,3245 4125,3245 4132.44,3252.44 C57.1@4132.44,3295 R65.2@4132.44,3342.44
CS2B_1: C34.1 C35.1 R91.1 U6.2 | length 233.6
  Bottom Layer w10: U6.2@1462.4,3158.58 1503.58,3158.58 1540,3195 C34.1@1580,3195
  Bottom Layer w20: C34.1@1580,3195 1629.88,3195 1632.44,3192.44 C35.1@1632.44,3145
CS2B_2: C55.1 C56.1 R121.1 U8.2 | length 233.6
  Bottom Layer w10: U8.2@3962.4,3158.58 4003.58,3158.58 4040,3195 C55.1@4080,3195
  Bottom Layer w20: C55.1@4080,3195 4129.88,3195 4132.44,3192.44 C56.1@4132.44,3145
ENABLE: J2.1 Q5.1 R10.1 R18.2 U6.10 U8.10 | length 4717.2
  Signal Layer 2 w20: v2(1550,2975) 1635,3060 1635,3315 1720,3400 v2(1850,3400) ; J2.1@1900,3800 1900,3450 v2(1850,3400) ; v2(4050,2975) 4105,3030 4105,3165 4005,3265 3530,3265 3405,3390 3280,3390 2760,2870 2540,2870 2490,2820 v2(2400,2820) 2305,2820 1850,3275 v2(1850,3400)
  Bottom Layer w10: U6.10@1462.4,3001.1 1523.9,3001.1 v2(1550,2975) ; U8.10@3962.4,3001.1 4023.9,3001.1 v2(4050,2975)
  Bottom Layer w20: v2(1850,3400) 1850,3295 1907.4,3237.6 Q5.1@1942.76,3237.6 1942.76,3212.24 1960,3195 R10.1@1960,3170 ; v2(2400,2820) R18.2@2467.44,2820
HO1_1: R72.1 R81.1 U7.12 | length 1637.4
  Signal Layer 5 w20: v2(415,1495) 450,1530 450,1805 ; v2(415,1805) 450,1805 ; v2(1185,2370) 770,2370 450,2050 450,1805
  Bottom Layer w10: v2(1185,2370) 1248.82,2370 U7.12@1248.82,2343.31
  Bottom Layer w20: v2(415,1495) R72.1@452.44,1495 ; v2(415,1805) R81.1@452.44,1805
HO1_2: R102.1 R111.1 U9.12 | length 1637.6
  Signal Layer 5 w20: v2(2915,1495) 2950,1530 2950,1805 ; v2(2915,1805) 2950,1805 ; v2(3685,2370) 3270,2370 2950,2050 2950,1805
  Bottom Layer w10: v2(3685,2370) 3748.82,2370 U9.12@3748.82,2343.31
  Bottom Layer w20: v2(2915,1495) R102.1@2950,1495 ; v2(2915,1805) R111.1@2952.44,1805 R111.1@2955,1805
HO2_1: R89.1 R98.1 U7.9 | length 1246.6
  Signal Layer 5 w20: v2(1425,2395) 1695,2125 1695,1805 ; v2(1665,1495) 1695,1525 1695,1805 ; v2(1665,1805) 1695,1805
  Bottom Layer w10: U7.9@1351.18,2343.31 1351.18,2381.18 1365,2395 v2(1425,2395)
  Bottom Layer w20: v2(1665,1495) R89.1@1702.44,1495 ; v2(1665,1805) R98.1@1702.44,1805
HO2_2: R119.1 R128.1 U9.9 | length 1251.7
  Signal Layer 5 w20: v2(3925,2395) 4195,2125 4195,1805 ; v2(4165,1495) 4195,1525 4195,1805 ; v2(4165,1805) 4195,1805
  Bottom Layer w10: U9.9@3851.18,2343.31 3851.18,2381.18 3865,2395 v2(3925,2395)
  Bottom Layer w20: v2(4165,1495) R119.1@4202.44,1495 R119.1@4205,1495 ; v2(4165,1805) R128.1@4202.44,1805 R128.1@4205,1805
IMON: C15.1 D4.1 D7.1 D8.1 D11.1 R25.2 R28.2 U4.4 | length 6482.6
  Signal Layer 2 w20: v2(2525,3015) 2550,3040 v2(2550,3700) ; v2(3280,3585) 3325,3630 v2(3325,3800)
  Signal Layer 5 w20: v2(780,3600) 780,3695 815,3730 2520,3730 v2(2550,3700) 2750,3700 2850,3800 v2(3325,3800) 3500,3800 3600,3700 4417.5,3700 4651.25,3466.25 4878.75,3466.25 5005,3340 5005,3145 4925,3065 v2(4925,3010)
  Bottom Layer w15: R25.2@2465.71,2969.29 U4.4@2524.41,2969.29 2524.41,3014.41 v2(2525,3015)
  Bottom Layer w20: D4.1@825,3451.65 780,3496.65 v2(780,3600) D7.1@825,3600 ; C15.1@2405,2980 2407.44,2977.56 R25.2@2460,2977.56 ; D8.1@3325,3451.65 3280,3496.65 v2(3280,3585) 3296.65,3601.65 D11.1@3325,3601.65 ; v2(4925,3010) R28.2@4925,3045
ISETA: C31.1 C52.1 R20.1 R22.1 R26.1 U6.45 U8.45 | length 5419.8
  Signal Layer 5 w20: v2(1365,3350) 1430,3415 1780,3415 2045,3150 2150,3150 ; v2(2115,3300) 2150,3265 2150,3150 ; v2(3865,3350) 3865,3400 ; v2(4980,3010) 4940,2970 4900,2970 4810,3060 4660,3060 4605,3115 4605,3385 4510,3480 4265,3480 4185,3400 3865,3400 ; 2150,3150 2920,3150 3020,3250 3020,3540 3210,3730 3455,3730 3785,3400 3865,3400
  Bottom Layer w10: U6.45@1349.21,3232.4 1349.21,3334.04 1354.87,3339.7 1354.87,3339.87 v2(1365,3350) ; U8.45@3849.21,3232.4 3849.21,3334.04 3854.87,3339.7 3854.87,3339.87 v2(3865,3350)
  Bottom Layer w20: v2(1365,3350) C31.1@1365,3387.44 ; v2(2115,3300) 2115,3340 2110,3345 R20.1@2187.44,3345 ; v2(3865,3350) C52.1@3865,3387.44 ; v2(4980,3010) R26.1@4980,3047.44 R26.1@4980,3050
LO1_1: Q7.1 R78.1 R79.1 U6.20 | length 2671.9
  Signal Layer 5 w20: v2(775,1495) 805,1525 805,1805 ; v2(775,1805) 805,1805 ; v2(880,3500) 880,3415 1090,3205 1090,2995 1195,2890 1230,2890 v2(1260,2860) 1260,2755 1157.5,2652.5 1157.5,2555 1275,2437.5 1275,2305 805,1835 805,1805
  Bottom Layer w10: v2(1260,2860) 1270.47,2870.47 U6.20@1270.47,2911.54
  Bottom Layer w20: v2(775,1495) R78.1@812.44,1495 ; v2(775,1805) R79.1@812.44,1805 ; v2(880,3500) Q7.1@910,3500
LO1_2: Q9.1 R108.1 R109.1 U8.20 | length 2672
  Signal Layer 5 w20: v2(3275,1495) 3305,1525 3305,1805 ; v2(3275,1805) 3305,1805 ; v2(3380,3500) 3380,3415 3590,3205 3590,2995 3695,2890 3730,2890 v2(3760,2860) 3760,2755 3657.5,2652.5 3657.5,2555 3775,2437.5 3775,2305 3305,1835 3305,1805
  Bottom Layer w10: v2(3760,2860) 3770.47,2870.47 U8.20@3770.47,2911.54
  Bottom Layer w20: v2(3275,1495) R108.1@3312.44,1495 R108.1@3315,1495 ; v2(3275,1805) R109.1@3310,1805 ; v2(3380,3500) Q9.1@3410,3500
LO2_1: Q8.1 R95.1 R96.1 U6.17 | length 3066.6
  Signal Layer 5 w20: v2(880,3650) 950,3580 950,3440 1150,3240 1150,3000 1210,2940 1260,2940 v2(1340,2860) 1360,2840 1360,2775 1530,2605 1850,2605 2055,2400 2055,1805 ; v2(2025,1495) 2055,1525 2055,1805 ; v2(2025,1805) 2055,1805
  Bottom Layer w10: U6.17@1329.53,2911.54 1329.53,2870.47 v2(1340,2860)
  Bottom Layer w20: v2(880,3650) Q8.1@915,3650 ; v2(2025,1495) R95.1@2062.44,1495 ; v2(2025,1805) R96.1@2062.44,1805
LO2_2: Q10.1 R125.1 R126.1 U8.17 | length 3051.6
  Signal Layer 5 w20: v2(3380,3595) 3385,3595 3450,3530 3450,3440 3650,3240 3650,3000 3710,2940 3760,2940 v2(3840,2860) 3860,2840 3860,2775 4030,2605 4350,2605 4555,2400 4555,1805 ; v2(4525,1495) 4555,1525 4555,1805 ; v2(4525,1805) 4555,1805
  Bottom Layer w10: U8.17@3829.53,2911.54 3829.53,2870.47 v2(3840,2860)
  Bottom Layer w20: v2(3380,3595) 3380,3615 Q10.1@3415,3650 ; v2(4525,1495) R125.1@4562.44,1495 ; v2(4525,1805) R126.1@4562.44,1805 R126.1@4565,1805
NetC2_1: C2.1 U1.7 | length 120.8
  Bottom Layer w20: U1.7@4775,3228.35 4775,3295 4785,3305 C2.1@4785,3345
NetC4_1: C4.1 C7.2 R5.1 | length 153.1
  Bottom Layer w20: C4.1@4657.56,3455 4657.56,3402.44 4665,3395 C7.2@4665,3352.56 C7.2@4665,3350 ; C4.1@4660,3455 R5.1@4705,3455
NetC5_1: C5.1 U1.6 | length 71.7
  Bottom Layer w20: U1.6@4725,3228.35 C5.1@4725,3297.44 C5.1@4725,3300
NetC7_1: C7.1 R6.1 R9.2 U1.5 | length 203.1
  Bottom Layer w20: R9.2@4600,3230 4601.65,3228.35 U1.5@4675,3228.35 ; R9.2@4602.56,3232.44 4602.56,3297.44 C7.1@4665,3297.44
NetC10_1: C10.1 Q3.3 R14.1 R16.1 R17.1 U3.4 | length 673.5
  Signal Layer 2 w20: v2(2470,3425) 2470,3270 v2(2500,3240)
  Bottom Layer w20: C10.1@2377.56,3220 2440,3220 ; U3.4@2424.13,3422.4 2467.4,3422.4 v2(2470,3425) ; R17.1@2442.56,3275 2442.56,3167.44 Q3.3@2460,3150 ; 2445,3240 v2(2500,3240) 2520,3240 2555,3275 R16.1@2555,3332.44 ; R16.1@2562.44,3332.44 R14.1@2615,3332.44
NetC10_2: C10.2 C11.1 R20.2 U3.1 | length 258.1
  Bottom Layer w20: R20.2@2242.6,3347.6 U3.1@2315.87,3347.6 ; R20.2@2245,3345 2245,3315 2255,3305 2255,3240 2275,3220 C10.2@2322.44,3220
NetC11_2: C11.2 R17.2 | length 82.4
  Bottom Layer w20: C11.2@2305,3275 C11.2@2307.56,3275 R17.2@2387.44,3275
NetC14_1: C14.1 R21.2 R23.2 U3.3 | length 215.9
  Bottom Layer w20: C14.1@2242.4,3422.4 U3.3@2315.87,3422.4 2315.87,3489.13 R21.2@2310,3495 ; C14.1@2242.56,3427.56 R23.2@2242.56,3495
NetC17_2: C17.2 D2.1 D3.2 | length 139
  Bottom Layer w20: D3.2@4910,3385 4911.65,3386.65 D2.1@4980,3386.65 C17.2@4980,3455
NetC18_1: C18.1 R26.2 R27.1 R28.1 | length 164.9
  Bottom Layer w20: R28.1@4925,3102.56 C18.1@4925,3157.44 ; C18.1@4925,3160 C18.1@4925,3157.44 ; R26.2@4980,3105 R27.1@4980,3157.44 C18.1@4925,3157.44
NetC19_1: C19.1 D2.2 R27.2 | length 133.3
  Bottom Layer w20: R27.2@4980,3210 R27.2@4980,3212.56 D2.2@4980,3343.35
